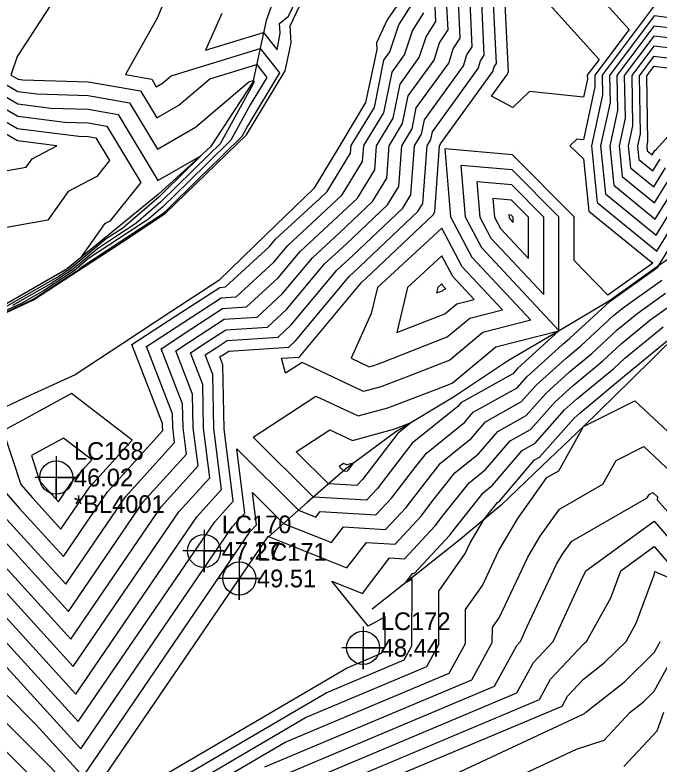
# Model space of a CAD drawing. Extents: x 2188792 to 2191981, y 386090 to 389710.
# Drawn here: x 2190049.8 to 2190140.8, y 387762.9 to 387868.7 of the extents above; entities that cross this region are included whole.
import ezdxf

# ---------------------------------------------------------------- set-up
doc = ezdxf.new("R2010")
doc.units = 0
for name, color, linetype in [('DTM Contours Major', 7, 'Continuous'), ('DTM Contours Minor', 7, 'Continuous'), ('Exist DTM Breakline Cogo Elevation', 7, 'Continuous'), ('Exist DTM Breakline Cogo Number', 7, 'Continuous'), ('Exist DTM Breakline Cogo Point CELL', 7, 'Continuous'), ('Exist DTM Breakline Underwater Cogo Elevation', 7, 'Continuous'), ('Exist DTM Breakline Underwater Cogo Number', 7, 'Continuous'), ('Exist DTM Breakline Underwater Cogo Point CELL', 7, 'Continuous'), ('Exist DTM QL2 LIDAR Elevation Point', 7, 'Continuous'), ('Exist DTM Regular Point Underwater CELL', 7, 'Continuous'), ('Exist DTM Regular Point Underwater Cogo Comment', 7, 'Continuous'), ('Exist DTM Regular Point Underwater Cogo Elevation', 7, 'Continuous'), ('Exist DTM Regular Point Underwater Cogo Number', 7, 'Continuous'), ('PH Exist DTM Breakline', 7, 'Continuous')]:
    doc.layers.add(name, color=color, linetype=linetype)

msp = doc.modelspace()

# ---------------------------------------------------------------- linework, layer by layer
at = {"layer": 'DTM Contours Major'}
for points in [[(2190046.83, 387795.89), (2190057.31, 387784.41), (2190067.9, 387799.91), (2190073.99, 387806.63), (2190073.52, 387810.4), (2190073.46, 387813.73), (2190070.42, 387821.54), (2190074.78, 387824.37), (2190079.12, 387827.2), (2190082.49, 387827.43), (2190086.98, 387831.54), (2190090.07, 387835.25), (2190094.7, 387839.53), (2190098.16, 387842.81), (2190100.61, 387846.8), (2190100.86, 387850.21), (2190103.23, 387854.09), (2190104.2, 387858.92), (2190106.91, 387862.67), (2190107.86, 387865.58), (2190109.26, 387867.77), (2190109.11, 387870.82)], [(2190133.34, 387870.19), (2190136.56, 387866.63), (2190131.71, 387860.17), (2190131.74, 387858.51), (2190130.12, 387851.03), (2190129.18, 387851.13), (2190128.2, 387850.19), (2190130.12, 387848.35), (2190130.86, 387840.95), (2190139.9, 387833.61), (2190133.56, 387829.1), (2190128.79, 387833.99), (2190128.78, 387840.17), (2190120.09, 387848.93), (2190110.53, 387849.76), (2190111.33, 387840.17), (2190114.34, 387834.45), (2190122.67, 387825.55), (2190115.91, 387823.81), (2190111.21, 387819.93), (2190105.45, 387817.67), (2190101.46, 387816.16), (2190099.04, 387815.51), (2190090.35, 387819.61), (2190088.02, 387818.09), (2190087.43, 387820.18), (2190089.94, 387820.35), (2190090.04, 387820.45), (2190098.74, 387830.88), (2190099.37, 387831.47), (2190108.86, 387840.46), (2190109.12, 387840.88), (2190109.79, 387850.19), (2190109.88, 387850.32), (2190109.91, 387850.49), (2190117.31, 387860.71), (2190117.51, 387861.33), (2190117.81, 387861.8), (2190117.41, 387870.34)], [(2190146.58, 387863.49), (2190140.04, 387864.25), (2190136.93, 387860.11), (2190137.06, 387852.99), (2190136.45, 387850.18), (2190136.76, 387847.06), (2190140.05, 387844.38), (2190141.72, 387847.08)], [(2190046.19, 387860.18), (2190050.18, 387857.85), (2190052.84, 387857.51), (2190060.1, 387857.31), (2190065.93, 387856.28), (2190069.89, 387849.71), (2190075.28, 387852.82), (2190082.84, 387859.22), (2190083.45, 387859.41), (2190083.59, 387859.24), (2190083.37, 387858.87), (2190078.76, 387850.48), (2190077.21, 387848.97), (2190072.56, 387844.4), (2190070.4, 387842.28), (2190066.83, 387839.2), (2190064.12, 387837.43), (2190061.42, 387835.65), (2190057.86, 387832.69), (2190054.89, 387830.75), (2190049.43, 387827.62)], [(2190047.16, 387778.05), (2190059.06, 387765), (2190080.51, 387796.4), (2190082.26, 387798.33), (2190081.13, 387807.37), (2190089.85, 387798.72), (2190092.31, 387797.74), (2190092.92, 387798.54), (2190100.79, 387798.07), (2190103, 387800.44), (2190106.42, 387804.89), (2190107.91, 387806.78), (2190113.33, 387811.14), (2190114.54, 387812.55), (2190120.74, 387816.03), (2190122.11, 387817.57), (2190127.15, 387822.15), (2190128.2, 387823.02), (2190133.83, 387828.22), (2190133.89, 387828.27), (2190140.62, 387833.06), (2190140.68, 387833.11), (2190140.71, 387833.22), (2190145.52, 387841.02)], [(2190064.43, 387753.98), (2190090.85, 387769.46), (2190107.96, 387776.66), (2190109.65, 387779.74), (2190109.69, 387787.29), (2190113.41, 387792.61), (2190114.07, 387794.02), (2190116.1, 387797.45), (2190117.96, 387799.79), (2190118.23, 387800.01), (2190123.21, 387805.83), (2190123.9, 387806.22), (2190128.78, 387811.71), (2190129.63, 387812.47), (2190135.93, 387817.68), (2190136.49, 387818.19), (2190143.25, 387823.73)], [(2190076.45, 387752.04), (2190123.9, 387772), (2190125.46, 387774.84), (2190130.12, 387779.81), (2190130.32, 387779.97), (2190130.53, 387780.18), (2190133.96, 387786.34), (2190135.39, 387790.18), (2190140.12, 387793.6), (2190143.09, 387790.18)]]:
    msp.add_lwpolyline(points, dxfattribs=at)
at = {"layer": 'DTM Contours Minor'}
for points in [[(2190140.92, 387879.34), (2190140.33, 387870.18), (2190140.37, 387869.93), (2190140.12, 387869.96), (2190132.75, 387860.16), (2190132.8, 387857.41), (2190131.24, 387850.18), (2190132.04, 387842.17), (2190140.49, 387835.31), (2190144.76, 387842.23)], [(2190079.02, 387868.9), (2190076.7, 387863.68), (2190084.9, 387866.2), (2190086.83, 387863.75), (2190087.25, 387866.11), (2190087.15, 387867.48), (2190088.44, 387868.52), (2190091.04, 387874.07)], [(2190119.61, 387870.59), (2190120.48, 387871.28), (2190125.26, 387870.19), (2190132.33, 387862.4), (2190130.66, 387860.18), (2190130.67, 387859.61), (2190130.12, 387857.05), (2190122.47, 387857.84), (2190120.12, 387855.59), (2190117.12, 387857.19), (2190119.39, 387860.32), (2190119.44, 387860.48), (2190119.52, 387860.6), (2190119.06, 387870.25), (2190119.61, 387870.59)], [(2190041.44, 387791.31), (2190058.36, 387772.76), (2190075.46, 387797.8), (2190078.95, 387801.65), (2190077.87, 387810.26), (2190077.73, 387817.88), (2190076.65, 387820.67), (2190078.21, 387821.68), (2190079.76, 387822.69), (2190086.96, 387823.18), (2190088.82, 387824.89), (2190095.27, 387832.63), (2190097.5, 387834.69), (2190104.58, 387841.4), (2190105.71, 387843.25), (2190106.22, 387850.2), (2190107.22, 387851.83), (2190107.63, 387853.86), (2190113.15, 387861.49), (2190113.65, 387863.03), (2190114.39, 387864.19), (2190114.09, 387870.54)], [(2190041.56, 387787.69), (2190058.71, 387768.88), (2190077.99, 387797.1), (2190080.6, 387799.99), (2190079.33, 387810.21), (2190079.16, 387819.26), (2190078.72, 387820.38), (2190079.35, 387820.78), (2190079.97, 387821.19), (2190088.45, 387821.77), (2190089.43, 387822.67), (2190097, 387831.75), (2190098.44, 387833.08), (2190106.72, 387840.93), (2190107.42, 387842.06), (2190108.01, 387850.19), (2190108.55, 387851.08), (2190108.77, 387852.18), (2190115.23, 387861.1), (2190115.58, 387862.18), (2190116.1, 387862.99), (2190115.75, 387870.44)], [(2190043.24, 387792.84), (2190058.01, 387776.64), (2190072.94, 387798.51), (2190077.29, 387803.31), (2190076.42, 387810.3), (2190076.31, 387816.5), (2190074.57, 387820.96), (2190077.07, 387822.58), (2190079.55, 387824.19), (2190085.47, 387824.6), (2190088.2, 387827.11), (2190093.53, 387833.5), (2190096.57, 387836.3), (2190102.44, 387841.87), (2190104.01, 387844.43), (2190104.43, 387850.2), (2190105.89, 387852.59), (2190106.49, 387855.55), (2190111.07, 387861.88), (2190111.72, 387863.88), (2190112.68, 387865.38), (2190112.43, 387870.63)], [(2190070.72, 387870.23), (2190069.84, 387868.24), (2190065.39, 387860.25), (2190069.09, 387859.59), (2190069.73, 387858.53), (2190070.6, 387859.04), (2190071.82, 387860.07), (2190084.41, 387863.93), (2190087.14, 387860.48), (2190082.67, 387853.06), (2190081.81, 387851.49), (2190076.83, 387846.61), (2190076.1, 387845.89), (2190070.93, 387840.83), (2190070.48, 387840.44), (2190064.72, 387836.66), (2190058.95, 387832.88), (2190058.5, 387832.51), (2190052.7, 387828.71), (2190052.01, 387828.32), (2190043.65, 387824.42)], [(2190054.74, 387869.98), (2190050.07, 387862.82), (2190049.19, 387860.18), (2190050.2, 387859.59), (2190050.87, 387859.5), (2190060.1, 387859.24), (2190067.51, 387857.94), (2190069.81, 387854.12), (2190072.94, 387855.93), (2190077.33, 387859.64), (2190083.93, 387861.67), (2190085.37, 387859.86), (2190083.02, 387855.97), (2190080.28, 387850.99), (2190077.02, 387847.79), (2190074.33, 387845.15), (2190070.66, 387841.55), (2190068.66, 387839.82), (2190064.42, 387837.04), (2190060.18, 387834.27), (2190058.18, 387832.6), (2190053.8, 387829.73), (2190050.72, 387827.97), (2190044.44, 387825.04)], [(2190045.04, 387794.36), (2190057.66, 387780.52), (2190070.42, 387799.21), (2190075.64, 387804.97), (2190074.97, 387810.35), (2190074.88, 387815.11), (2190072.5, 387821.25), (2190075.93, 387823.48), (2190079.34, 387825.69), (2190083.98, 387826.01), (2190087.59, 387829.33), (2190091.8, 387834.38), (2190095.63, 387837.91), (2190100.3, 387842.34), (2190102.31, 387845.61), (2190102.64, 387850.21), (2190104.56, 387853.34), (2190105.34, 387857.23), (2190108.99, 387862.28), (2190109.79, 387864.73), (2190110.97, 387866.58), (2190110.77, 387870.73)], [(2190047.93, 387801.82), (2190050.42, 387798.95), (2190056.61, 387792.17), (2190062.86, 387801.32), (2190070.68, 387809.96), (2190070.61, 387810.49), (2190070.6, 387810.97), (2190066.27, 387822.12), (2190072.5, 387826.17), (2190078.7, 387830.2), (2190079.52, 387830.26), (2190085.75, 387835.98), (2190086.6, 387837), (2190092.83, 387842.75), (2190093.88, 387843.75), (2190097.2, 387849.17), (2190097.28, 387850.22), (2190100.56, 387855.6), (2190101.92, 387862.29), (2190102.76, 387863.45), (2190104, 387867.28), (2190105.84, 387870.16)], [(2190048.63, 387797.42), (2190056.96, 387788.29), (2190065.38, 387800.62), (2190072.33, 387808.29), (2190072.06, 387810.45), (2190072.03, 387812.35), (2190068.34, 387821.83), (2190073.64, 387825.27), (2190078.91, 387828.7), (2190081.01, 387828.84), (2190086.37, 387833.76), (2190088.33, 387836.12), (2190093.76, 387841.14), (2190096.02, 387843.28), (2190098.9, 387847.98), (2190099.07, 387850.22), (2190101.89, 387854.85), (2190103.06, 387860.6), (2190104.84, 387863.06), (2190105.93, 387866.43), (2190107.55, 387868.97)], [(2190141.92, 387868.32), (2190140.1, 387868.53), (2190133.8, 387860.14), (2190133.87, 387856.3), (2190132.54, 387850.18), (2190133.22, 387843.39), (2190140.38, 387837.58), (2190144, 387843.45)], [(2190143.48, 387866.71), (2190140.08, 387867.1), (2190134.84, 387860.13), (2190134.93, 387855.2), (2190133.84, 387850.18), (2190134.4, 387844.61), (2190140.27, 387839.85), (2190143.24, 387844.66)], [(2190145.03, 387865.1), (2190140.06, 387865.68), (2190135.88, 387860.12), (2190135.99, 387854.1), (2190135.15, 387850.18), (2190135.58, 387845.84), (2190140.16, 387842.12), (2190142.48, 387845.87)], [(2190148.13, 387861.88), (2190140.02, 387862.82), (2190137.97, 387860.09), (2190138.12, 387851.89), (2190137.75, 387850.18), (2190137.94, 387848.28), (2190139.94, 387846.65), (2190140.95, 387848.3)], [(2190149.69, 387860.27), (2190140, 387861.39), (2190139.02, 387860.08), (2190139.18, 387850.79), (2190139.05, 387850.18), (2190139.12, 387849.5), (2190139.83, 387848.92), (2190140.19, 387849.51), (2190140.43, 387849.73), (2190149.77, 387860.11)], [(2190040.19, 387860.19), (2190050.15, 387854.37), (2190056.79, 387853.53), (2190060.11, 387853.44), (2190062.77, 387852.97), (2190067.55, 387845.03), (2190063.18, 387839.56), (2190062.42, 387839.16), (2190059.04, 387834.39), (2190057.22, 387832.87), (2190057.09, 387832.79), (2190046.85, 387826.92)], [(2190043.19, 387860.18), (2190050.16, 387856.11), (2190054.82, 387855.52), (2190060.1, 387855.37), (2190064.35, 387854.62), (2190069.97, 387845.29), (2190076.02, 387848.79), (2190070.79, 387843.66), (2190070.13, 387843), (2190065, 387838.58), (2190063.83, 387837.81), (2190062.65, 387837.04), (2190057.54, 387832.78), (2190055.99, 387831.77), (2190048.14, 387827.27)], [(2190044.21, 387856.09), (2190050.13, 387852.63), (2190058.77, 387851.54), (2190060.11, 387851.5), (2190061.19, 387851.31), (2190063.13, 387848.1), (2190061.35, 387845.88), (2190057.3, 387843.75), (2190054.41, 387839.67), (2190045.08, 387838.06)], [(2190050.12, 387850.89), (2190048.42, 387851.88), (2190047.83, 387850.19), (2190046.2, 387846.27), (2190051.35, 387847.16), (2190052.18, 387848.33), (2190055.69, 387850.19), (2190050.12, 387850.89)], [(2190126.65, 387824.09), (2190126.64, 387840.15), (2190120.05, 387846.79), (2190112.79, 387847.43), (2190113.4, 387840.15), (2190115.68, 387835.81), (2190126.65, 387824.09)], [(2190124.5, 387829.19), (2190124.49, 387840.13), (2190120, 387844.66), (2190115.05, 387845.09), (2190115.47, 387840.13), (2190117.02, 387837.17), (2190124.5, 387829.19)], [(2190122.35, 387834.28), (2190122.35, 387840.11), (2190119.95, 387842.52), (2190117.32, 387842.75), (2190117.54, 387840.11), (2190118.37, 387838.53), (2190122.35, 387834.28)], [(2190120.2, 387839.37), (2190120.2, 387840.09), (2190119.91, 387840.39), (2190119.58, 387840.42), (2190119.61, 387840.09), (2190119.71, 387839.89), (2190120.2, 387839.37)], [(2190112.99, 387833.09), (2190110.12, 387838.57), (2190100.99, 387830.18), (2190100.12, 387826.51), (2190097.27, 387820.18), (2190099.84, 387818.97), (2190100.47, 387819.14), (2190101.5, 387819.53), (2190110.86, 387823.2), (2190114.06, 387825.84), (2190118.67, 387827.03), (2190112.99, 387833.09)], [(2190111.65, 387831.73), (2190110.12, 387834.65), (2190105.26, 387830.18), (2190103.75, 387823.82), (2190110.51, 387826.46), (2190112.22, 387827.87), (2190114.67, 387828.5), (2190111.65, 387831.73)], [(2190039.17, 387782.06), (2190052.75, 387768.42), (2190059.41, 387761.12), (2190083.03, 387795.7), (2190083.91, 387796.67), (2190083.34, 387801.22), (2190087.73, 387796.87), (2190094.5, 387794.15), (2190096.19, 387796.36), (2190102.14, 387796), (2190105.06, 387799.13), (2190107.72, 387802.61), (2190109.92, 387805.38), (2190114.31, 387808.91), (2190116.27, 387811.2), (2190121.37, 387814.06), (2190123.45, 387816.39), (2190127.65, 387820.21), (2190129.75, 387821.95), (2190134.37, 387826.22), (2190135.77, 387827.36), (2190141.17, 387831.21)], [(2190110.3, 387830.37), (2190110.12, 387830.72), (2190109.53, 387830.18), (2190109.35, 387829.41), (2190110.17, 387829.73), (2190110.37, 387829.9), (2190110.67, 387829.98), (2190110.3, 387830.37)], [(2190059.76, 387757.24), (2190085.55, 387794.99), (2190085.56, 387795.01), (2190085.55, 387795.07), (2190085.62, 387795.01), (2190096.69, 387790.57), (2190099.45, 387794.18), (2190103.49, 387793.94), (2190107.11, 387797.82), (2190109.03, 387800.33), (2190111.93, 387803.99), (2190115.29, 387806.69), (2190118.01, 387809.86), (2190122, 387812.1), (2190124.78, 387815.22), (2190128.14, 387818.28), (2190131.29, 387820.88), (2190134.9, 387824.21), (2190137.64, 387826.46), (2190141.73, 387829.37)], [(2190061.08, 387755.6), (2190096.61, 387776.43), (2190101.58, 387778.52), (2190102.07, 387779.42), (2190102.1, 387783.65), (2190099.7, 387782.37), (2190094.55, 387788.72), (2190098.88, 387786.98), (2190102.71, 387792), (2190104.84, 387791.87), (2190109.16, 387796.51), (2190110.34, 387798.05), (2190113.94, 387802.59), (2190116.27, 387804.46), (2190119.74, 387808.52), (2190122.64, 387810.14), (2190126.12, 387814.05), (2190128.64, 387816.34), (2190132.84, 387819.81), (2190135.43, 387822.21), (2190139.51, 387825.55), (2190142.28, 387827.52)], [(2190062.75, 387754.79), (2190093.73, 387772.95), (2190104.77, 387777.59), (2190105.86, 387779.58), (2190105.92, 387788.97), (2190104.93, 387788.44), (2190105.98, 387789.82), (2190106.2, 387789.8), (2190111.21, 387795.19), (2190111.65, 387795.77), (2190115.95, 387801.19), (2190117.25, 387802.24), (2190121.47, 387807.17), (2190123.27, 387808.18), (2190127.45, 387812.88), (2190129.13, 387814.41), (2190134.39, 387818.74), (2190135.96, 387820.2), (2190141.38, 387824.64)], [(2190091.97, 387800.58), (2190083.42, 387809.06), (2190092.31, 387814.85), (2190098.25, 387812.05), (2190102.46, 387813.19), (2190109.39, 387815.81), (2190111.55, 387816.66), (2190117.75, 387821.78), (2190126.64, 387824.07), (2190120.78, 387818.74), (2190120.11, 387817.99), (2190112.8, 387813.89), (2190112.35, 387813.36), (2190105.91, 387808.18), (2190105.11, 387807.17), (2190100.95, 387801.76), (2190099.44, 387800.13), (2190091.97, 387800.58)], [(2190057.76, 387815.22), (2190052.75, 387812.47), (2190048.12, 387809.93), (2190050.59, 387802.35), (2190052.22, 387800.47), (2190056.26, 387796.05), (2190060.34, 387802.02), (2190066.33, 387808.64), (2190057.76, 387815.22)], [(2190066.11, 387753.16), (2190087.97, 387765.98), (2190111.15, 387775.72), (2190113.44, 387779.9), (2190113.46, 387784.72), (2190115.84, 387788.11), (2190118.15, 387793.04), (2190120.82, 387797.57), (2190124.95, 387803.33), (2190126.61, 387804.28), (2190130.12, 387810.54), (2190137.36, 387814.19), (2190146.05, 387806.11)], [(2190094.08, 387802.44), (2190089.5, 387806.98), (2190094.27, 387810.09), (2190097.45, 387808.59), (2190103.46, 387810.21), (2190105.78, 387811.09), (2190103.9, 387809.58), (2190103.8, 387809.45), (2190098.9, 387803.07), (2190098.09, 387802.2), (2190094.08, 387802.44)], [(2190056.61, 387808.9), (2190054.27, 387807.62), (2190052.1, 387806.43), (2190053.25, 387802.88), (2190054.02, 387802), (2190055.91, 387799.93), (2190057.82, 387802.72), (2190060.62, 387805.82), (2190056.61, 387808.9)], [(2190085.09, 387762.49), (2190114.34, 387774.79), (2190117.22, 387780.06), (2190117.24, 387782.15), (2190118.26, 387783.62), (2190122.23, 387792.07), (2190123.99, 387795.05), (2190126.71, 387798.85), (2190132.86, 387802.38), (2190134.75, 387805.74), (2190138.64, 387807.71), (2190143.3, 387803.36)], [(2190097.63, 387805.39), (2190096.65, 387805.13), (2190096.22, 387805.33), (2190095.58, 387804.91), (2190096.2, 387804.3), (2190096.74, 387804.26), (2190096.85, 387804.38), (2190097.63, 387805.39)], [(2190082.21, 387759.01), (2190117.52, 387773.86), (2190120.68, 387779.62), (2190121.21, 387780.18), (2190122.13, 387782.19), (2190126.31, 387791.09), (2190127.16, 387792.53), (2190128.47, 387794.36), (2190139.11, 387800.49), (2190139.38, 387800.95), (2190139.91, 387801.22), (2190140.56, 387800.62), (2190140.53, 387800.18), (2190143.88, 387796.42)], [(2190079.33, 387755.52), (2190120.71, 387772.93), (2190123.07, 387777.23), (2190125.84, 387780.18), (2190130.12, 387789.51), (2190130.36, 387789.94), (2190130.45, 387790.18), (2190140.12, 387797.18), (2190146.19, 387790.18)], [(2190083.92, 387752.91), (2190127.09, 387771.06), (2190127.85, 387772.45), (2190130.12, 387774.87), (2190133.09, 387777.21), (2190136.13, 387780.18), (2190137.55, 387782.75), (2190140.12, 387789.62), (2190140.22, 387790.08), (2190150.12, 387785.73)], [(2190078.88, 387746.01), (2190130.07, 387769.93), (2190130.26, 387769.99), (2190130.43, 387770.18), (2190135.85, 387774.44), (2190140.12, 387778.61), (2190140.68, 387779.62), (2190140.97, 387780.18)], [(2189953.66, 387766.62), (2189960.1, 387768.56), (2189962.13, 387768.15), (2189970.1, 387765.63), (2189974.7, 387765.58), (2189980.11, 387769.11), (2189981.65, 387768.63), (2189990.11, 387767.46), (2189991.85, 387768.43), (2190000.11, 387767.62), (2190001.81, 387768.48), (2190010.11, 387775.45), (2190013.35, 387775), (2190020.48, 387775.39), (2190022.08, 387775.39), (2190029.5, 387776.39), (2190032.28, 387775.64), (2190038.76, 387778.47), (2190058.35, 387758.79)], [(2190082.81, 387743.31), (2190129.14, 387764.96), (2190133.03, 387766.26), (2190136.71, 387770.18), (2190138.62, 387771.68), (2190140.12, 387773.15), (2190142.61, 387777.68)], [(2189954.84, 387765.44), (2189960.1, 387767.02), (2189964.04, 387766.24), (2189970.1, 387764.32), (2189976.03, 387764.25), (2189980.11, 387766.92), (2189984.83, 387765.45), (2189990.11, 387764.72), (2189993.61, 387766.67), (2190000.11, 387766.03), (2190002.86, 387767.43), (2190010.11, 387773.51), (2190014.67, 387772.87), (2190020.65, 387773.2), (2190022.98, 387773.2), (2190029.12, 387774.03), (2190033.63, 387772.82), (2190038.34, 387774.88), (2190054.99, 387758.15)], [(2190135.8, 387762.53), (2190140.54, 387767.57), (2190141.49, 387770.18)]]:
    msp.add_lwpolyline(points, dxfattribs=at)
at = {"layer": 'Exist DTM Breakline Cogo Point CELL'}
msp.add_lwpolyline([(2190081.47, 387792.08), (2190081.47, 387786.08), (2190081.47, 387789.08), (2190084.47, 387789.08), (2190078.47, 387789.08)], dxfattribs=at)
msp.add_circle((2190081.47, 387789.08), 2.34, dxfattribs=at)
at = {"layer": 'Exist DTM Breakline Underwater Cogo Point CELL'}
msp.add_lwpolyline([(2190076.49, 387795.97), (2190076.49, 387789.97), (2190076.49, 387792.97), (2190079.49, 387792.97), (2190073.49, 387792.97)], dxfattribs=at)
msp.add_circle((2190076.49, 387792.97), 2.34, dxfattribs=at)
at = {"layer": 'Exist DTM QL2 LIDAR Elevation Point'}
for p, q in [((2190060.09, 387860.26), (2190060.09, 387860.26)), ((2190050.2, 387860.17), (2190050.2, 387860.17)), ((2190069.7, 387860.23), (2190069.7, 387860.23)), ((2190120.12, 387860.19), (2190120.12, 387860.19)), ((2190130.12, 387860.19), (2190130.12, 387860.19)), ((2190139.99, 387860.07), (2190139.99, 387860.07)), ((2190050.11, 387850.19), (2190050.11, 387850.19)), ((2190060.11, 387850.19), (2190060.11, 387850.19)), ((2190110.12, 387850.19), (2190110.12, 387850.19)), ((2190120.12, 387850.19), (2190120.12, 387850.19)), ((2190130.12, 387850.19), (2190130.12, 387850.19)), ((2190139.77, 387850.18), (2190139.77, 387850.18)), ((2190110.12, 387840.18), (2190110.12, 387840.18)), ((2190130.12, 387840.18), (2190130.12, 387840.18)), ((2190119.9, 387840.09), (2190119.9, 387840.09)), ((2190100.12, 387830.18), (2190100.12, 387830.18)), ((2190110.12, 387830.18), (2190110.12, 387830.18)), ((2190080.12, 387820.18), (2190080.12, 387820.18)), ((2190090.12, 387820.18), (2190090.12, 387820.18)), ((2190100.12, 387820.18), (2190100.12, 387820.18)), ((2190070.13, 387810.51), (2190070.13, 387810.51)), ((2190080.12, 387810.18), (2190080.12, 387810.18)), ((2190140.12, 387800.18), (2190140.12, 387800.18)), ((2190130.12, 387790.18), (2190130.12, 387790.18)), ((2190140.12, 387790.18), (2190140.12, 387790.18)), ((2190120.12, 387780.18), (2190120.12, 387780.18)), ((2190130.12, 387780.18), (2190130.12, 387780.18)), ((2190140.12, 387780.18), (2190140.12, 387780.18)), ((2190130.12, 387770.18), (2190130.12, 387770.18)), ((2190140.12, 387770.18), (2190140.12, 387770.18))]:
    msp.add_line(p, q, dxfattribs=at)
at = {"layer": 'Exist DTM Regular Point Underwater CELL'}
for points in [[(2190055.6, 387806.34), (2190055.6, 387800.34), (2190055.6, 387803.34), (2190058.6, 387803.34), (2190052.6, 387803.34)], [(2190098.97, 387782.29), (2190098.97, 387776.29), (2190098.97, 387779.29), (2190101.97, 387779.29), (2190095.97, 387779.29)]]:
    msp.add_lwpolyline(points, dxfattribs=at)
for centre in [(2190055.6, 387803.34), (2190098.97, 387779.29)]:
    msp.add_circle(centre, 2.34, dxfattribs=at)
at = {"layer": 'PH Exist DTM Breakline'}
for points in [[(2190109.83, 387900.59), (2190103.31, 387896.03), (2190096.8, 387891.47), (2190089.8, 387880.6), (2190087.53, 387874.25), (2190085.26, 387867.9), (2190083.4, 387859.17), (2190077.38, 387850.03), (2190070.01, 387843.33), (2190063.6, 387838.1), (2190057.19, 387832.88), (2190046.83, 387826.92), (2190039, 387826.39), (2190031.12, 387828.83), (2190020.08, 387833.12), (2190011.16, 387836.09), (2190002.3, 387841.82), (2190001.02, 387844.51), (2189997.21, 387848.98), (2189990.11, 387860.19)], [(2190043.46, 387824.28), (2190052.38, 387828.42), (2190058.59, 387832.48), (2190064.8, 387836.55), (2190071.01, 387840.62), (2190076.76, 387846.17), (2190082.51, 387851.73), (2190087.96, 387860.77), (2190088.79, 387864.72), (2190088.66, 387867.14), (2190091.89, 387874.02)], [(2190104.51, 387871.09), (2190102.37, 387868), (2190100.85, 387864.75), (2190100.9, 387863.79), (2190099.33, 387856.3), (2190095.67, 387850.23), (2190092.01, 387844.16), (2190085.29, 387837.66), (2190078.57, 387831.16), (2190071.79, 387826.73), (2190065.02, 387822.29), (2190058.25, 387817.86), (2190051.98, 387814.95), (2190045.72, 387812.04)], [(2190152.64, 387841.52), (2190147.5, 387837.87), (2190140.59, 387833.14), (2190133.81, 387828.31), (2190126.66, 387824.08), (2190119.51, 387819.85), (2190111.76, 387814.7), (2190103.61, 387809.78), (2190096.53, 387804.59), (2190091.06, 387799.79), (2190085.59, 387794.98)], [(2190150.12, 387830.18), (2190143.45, 387823.63), (2190136.79, 387817.08), (2190130.12, 387810.54), (2190124.3, 387804.98), (2190118.48, 387799.43), (2190112.44, 387794.41), (2190106.35, 387789.57), (2190100.26, 387784.73)]]:
    msp.add_lwpolyline(points, dxfattribs=at)

# ---------------------------------------------------------------- texts
at = {"layer": 'Exist DTM Breakline Cogo Elevation'}
msp.add_text('49.51', height=2.5, dxfattribs=at).set_placement((2190083.97, 387787.83))
at = {"layer": 'Exist DTM Breakline Cogo Number'}
msp.add_text('LC171', height=2.5, dxfattribs=at).set_placement((2190083.97, 387791.58))
at = {"layer": 'Exist DTM Breakline Underwater Cogo Elevation'}
msp.add_text('47.27', height=2.5, dxfattribs=at).set_placement((2190078.99, 387791.72))
at = {"layer": 'Exist DTM Breakline Underwater Cogo Number'}
msp.add_text('LC170', height=2.5, dxfattribs=at).set_placement((2190078.99, 387795.47))
at = {"layer": 'Exist DTM Regular Point Underwater Cogo Comment'}
msp.add_text('*BL4001', height=2.5, dxfattribs=at).set_placement((2190058.1, 387798.34))
at = {"layer": 'Exist DTM Regular Point Underwater Cogo Elevation'}
for s, p in [('46.02', (2190058.1, 387802.09)), ('48.44', (2190101.47, 387778.04))]:
    msp.add_text(s, height=2.5, dxfattribs=at).set_placement(p)
at = {"layer": 'Exist DTM Regular Point Underwater Cogo Number'}
for s, p in [('LC168', (2190058.1, 387805.84)), ('LC172', (2190101.47, 387781.79))]:
    msp.add_text(s, height=2.5, dxfattribs=at).set_placement(p)

doc.saveas('drawing.dxf')
